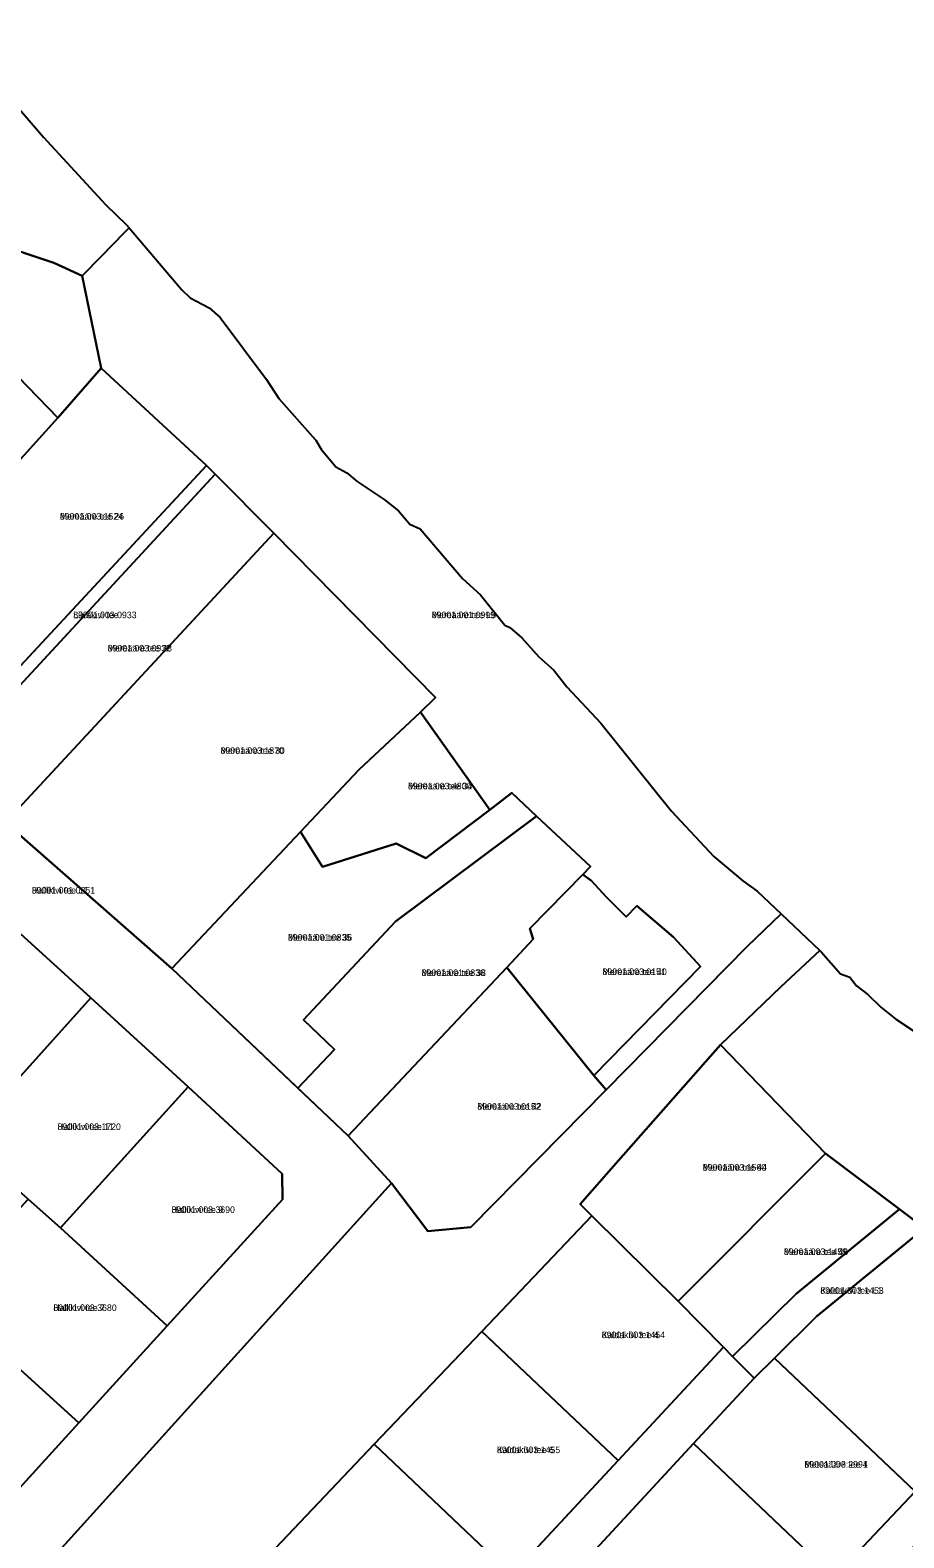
# Model space of a CAD drawing. Extents: x 526849 to 562296, y 6591741 to 6618546.
# Drawn here: x 550573.7 to 550773.8, y 6599050.2 to 6599395.6 of the extents above; entities that cross this region are included whole.
import ezdxf

# ---------------------------------------------------------------- set-up
doc = ezdxf.new("R2010")
doc.units = 0
for name, color, linetype in [('L_AADRESS', 7, 'Continuous'), ('PIIR', 7, 'Continuous'), ('TUNNUS', 7, 'Continuous')]:
    doc.layers.add(name, color=color, linetype=linetype)

msp = doc.modelspace()

# ---------------------------------------------------------------- linework, layer by layer
at = {"layer": 'PIIR'}
for points in [[(550549.04, 6599351.83), (550528.35, 6599369.9), (550549.32, 6599389.11), (550555.84, 6599395.08), (550556.4, 6599395.59), (550567.95, 6599381.35), (550576.84, 6599371.11), (550590.97, 6599355.63), (550595.81, 6599351.02), (550596.43, 6599350.3), (550595.36, 6599349.21), (550590.01, 6599343.77), (550585.65, 6599339.33), (550579.2, 6599342.29), (550572.05, 6599344.67), (550552.5, 6599350.29)], [(550702.85, 6599156.09), (550727.28, 6599181.05), (550721.06, 6599187.81), (550712.73, 6599194.98), (550710.23, 6599192.48), (550705.64, 6599197.07), (550702.3, 6599200.67), (550700.35, 6599202.18), (550702.06, 6599203.99), (550689.74, 6599215.54), (550684.09, 6599220.83), (550679.06, 6599217), (550663.17, 6599239.38), (550666.56, 6599242.67), (550629.58, 6599280.38), (550616.14, 6599293.84), (550614.16, 6599295.87), (550590.03, 6599318.17), (550585.65, 6599339.33), (550590.01, 6599343.77), (550595.36, 6599349.21), (550596.43, 6599350.3), (550608.51, 6599336.1), (550610.42, 6599334.28), (550614.71, 6599331.97), (550617.25, 6599329.75), (550627.88, 6599315.54), (550630.74, 6599311.18), (550638.44, 6599302.46), (550639.15, 6599301.65), (550640.42, 6599299.59), (550643.72, 6599295.57), (550646.26, 6599294.19), (550648.64, 6599292.18), (550654.83, 6599288.05), (550658.11, 6599285.46), (550660.7, 6599282.44), (550663.08, 6599281.33), (550672.77, 6599269.96), (550676.9, 6599266.2), (550682.5, 6599259.27), (550683.62, 6599258.74), (550686.37, 6599256.36), (550690.23, 6599252.02), (550693.67, 6599249), (550696.69, 6599245.14), (550704.47, 6599236.83), (550720.66, 6599216.67), (550730.34, 6599206.3), (550736.96, 6599200.74), (550740.29, 6599198.36), (550745.79, 6599193.13), (550737.98, 6599185.65), (550705.7, 6599152.83)], [(550510.77, 6599309.88), (550541.54, 6599342.64), (550559.43, 6599328.07), (550580.1, 6599306.74), (550556.65, 6599280.86), (550550.6, 6599274.25)], [(550580.1, 6599306.74), (550590.03, 6599318.17), (550614.16, 6599295.87), (550565.51, 6599243.53), (550546.92, 6599260.6), (550561.44, 6599276.48), (550556.65, 6599280.87)], [(550614.16, 6599295.87), (550616.14, 6599293.84), (550553.42, 6599226.1), (550551.1, 6599228), (550565.51, 6599243.53)], [(550616.14, 6599293.84), (550629.58, 6599280.38), (550568.13, 6599214.03), (550553.42, 6599226.1)], [(550666.56, 6599242.67), (550663.17, 6599239.38), (550649.05, 6599226.15), (550606.23, 6599180.62), (550568.13, 6599214.03), (550629.58, 6599280.38)], [(550649.05, 6599226.15), (550663.17, 6599239.38), (550679.06, 6599217), (550664.35, 6599205.91), (550657.54, 6599209.25), (550640.71, 6599203.94), (550635.68, 6599211.93)], [(550635.09, 6599153.18), (550606.23, 6599180.62), (550635.68, 6599211.93), (550640.71, 6599203.94), (550657.54, 6599209.25), (550664.35, 6599205.91), (550679.06, 6599217), (550684.09, 6599220.83), (550689.74, 6599215.54), (550657.46, 6599191.39), (550636.32, 6599168.88), (550643.49, 6599162.06)], [(550657.46, 6599191.39), (550689.74, 6599215.54), (550702.06, 6599203.99), (550700.35, 6599202.18), (550688.21, 6599189.79), (550688.99, 6599187.33), (550682.89, 6599180.84), (550646.61, 6599142.26), (550635.09, 6599153.18), (550643.49, 6599162.06), (550636.32, 6599168.88)], [(550682.89, 6599180.84), (550688.99, 6599187.33), (550688.21, 6599189.79), (550700.35, 6599202.18), (550702.3, 6599200.67), (550705.64, 6599197.07), (550710.23, 6599192.48), (550712.73, 6599194.98), (550721.06, 6599187.81), (550727.28, 6599181.05), (550702.85, 6599156.09)], [(550587.67, 6599173.92), (550558.23, 6599141.18), (550550.11, 6599132.57), (550556.45, 6599126.81), (550543.75, 6599112.69), (550515.18, 6599138.68), (550528.42, 6599153.26), (550536.04, 6599161.3), (550540.8, 6599166.48), (550548.07, 6599175.04), (550565.46, 6599194.05)], [(550702.85, 6599156.09), (550705.7, 6599152.83), (550674.7, 6599121.39), (550664.84, 6599120.43), (550656.49, 6599131.43), (550646.61, 6599142.26), (550682.89, 6599180.84)], [(550573.29, 6599127.75), (550564.86, 6599135.15), (550556.45, 6599126.81), (550550.11, 6599132.57), (550558.23, 6599141.18), (550587.67, 6599173.92), (550609.92, 6599153.53), (550580.7, 6599121.23)], [(550755.88, 6599138.22), (550722.16, 6599104.4), (550702.4, 6599123.99), (550699.72, 6599126.6), (550708.47, 6599136.67), (550731.84, 6599163.13)], [(550631.49, 6599133.6), (550631.57, 6599127.67), (550605.11, 6599098.78), (550580.7, 6599121.23), (550609.92, 6599153.53)], [(550755.88, 6599138.22), (550772.85, 6599125.45), (550749.19, 6599106.08), (550734.64, 6599091.74), (550732.57, 6599093.84), (550722.16, 6599104.4)], [(550580.7, 6599121.23), (550605.11, 6599098.78), (550584.88, 6599076.56), (550553, 6599105.5), (550573.29, 6599127.75)], [(550734.64, 6599091.74), (550749.19, 6599106.08), (550772.85, 6599125.45), (550778.61, 6599121.12), (550753.87, 6599100.87), (550744.26, 6599091.38), (550739.56, 6599086.74)], [(550677.17, 6599097.47), (550702.4, 6599123.99), (550722.16, 6599104.4), (550732.57, 6599093.84), (550708.39, 6599067.87)], [(550753.87, 6599100.87), (550778.61, 6599121.12), (550810.71, 6599097.21), (550776.42, 6599060.82), (550744.26, 6599091.38)], [(550647.29, 6598924.33), (550671.83, 6598950.06), (550691, 6598970.16), (550695.83, 6598975.29), (550726.95, 6599008.32), (550757.9, 6599041.17), (550776.42, 6599060.82), (550810.71, 6599097.21), (550835.74, 6599107.84), (550817.42, 6599092.12), (550794.95, 6599068.26), (550730.49, 6598999.81), (550671.85, 6598937.55), (550653.47, 6598918.39)], [(550553, 6599105.5), (550584.88, 6599076.56), (550566.59, 6599056.47), (550562.29, 6599056.43), (550532.65, 6599083.45)], [(550652.57, 6599071.62), (550677.17, 6599097.47), (550708.39, 6599067.87), (550684.05, 6599041.72)], [(550732.57, 6599093.84), (550734.64, 6599091.74), (550739.56, 6599086.74), (550725.7, 6599071.77), (550694.92, 6599038.5), (550663.72, 6599004.78), (550663.17, 6599004.19), (550640.31, 6598980.12), (550611.24, 6598949.51), (550609.79, 6598950.89), (550633.53, 6598975.89), (550626.28, 6598982.77), (550636.59, 6598993.67), (550638.04, 6598992.29), (550656.06, 6599011.65), (550684.05, 6599041.72), (550708.39, 6599067.87)], [(550757.9, 6599041.17), (550725.7, 6599071.77), (550739.56, 6599086.74), (550744.26, 6599091.38), (550776.42, 6599060.82)], [(550624.26, 6599041.87), (550652.57, 6599071.62), (550684.05, 6599041.72), (550656.06, 6599011.65)], [(550694.92, 6599038.5), (550725.7, 6599071.77), (550757.9, 6599041.17), (550726.95, 6599008.32)]]:
    msp.add_lwpolyline(points, close=True, dxfattribs=at)
for points in [[(550572.05, 6599344.67), (550579.2, 6599342.29), (550585.65, 6599339.33), (550590.03, 6599318.17), (550580.1, 6599306.74), (550559.43, 6599328.07)], [(550568.13, 6599214.03), (550606.23, 6599180.65), (550646.61, 6599142.26), (550656.49, 6599131.43), (550566.61, 6599032.03)], [(550566.59, 6599056.47), (550584.88, 6599076.56), (550605.11, 6599098.78), (550631.57, 6599127.67), (550631.49, 6599133.6), (550609.92, 6599153.53), (550587.67, 6599173.92), (550565.46, 6599194.05)], [(550566.61, 6599032.03), (550656.49, 6599131.43), (550664.84, 6599120.43), (550674.7, 6599121.39), (550705.7, 6599152.83), (550737.98, 6599185.65), (550745.79, 6599193.13), (550754.59, 6599184.78), (550745.65, 6599176.4), (550731.84, 6599163.13), (550708.47, 6599136.67), (550699.72, 6599126.6), (550702.4, 6599123.99), (550677.17, 6599097.47), (550652.57, 6599071.62), (550624.26, 6599041.87)], [(550778.61, 6599121.12), (550772.85, 6599125.45), (550755.88, 6599138.22), (550731.84, 6599163.13), (550745.65, 6599176.4), (550754.59, 6599184.78), (550754.95, 6599184.44), (550759.37, 6599179.41), (550761.46, 6599178.67), (550762.99, 6599176.66), (550765.58, 6599174.65), (550768.55, 6599171.75), (550772.04, 6599169), (550778.34, 6599164.82)]]:
    msp.add_lwpolyline(points, dxfattribs=at)

# ---------------------------------------------------------------- texts
at = {"layer": 'L_AADRESS'}
for s, p in [('Mereääre tee 26', (550580.54, 6599283.47)), ('Liivakivi tee', (550583.62, 6599260.87)), ('Mereääre tee L5', (550665.72, 6599260.88)), ('Mereääre tee 28', (550591.5, 6599253.25)), ('Mereääre tee 30', (550617.35, 6599229.8)), ('Mereääre tee 34', (550660.29, 6599221.66)), ('Hallikivi tee L1', (550574.12, 6599197.79)), ('Mereääre tee 36', (550632.79, 6599187)), ('Mereääre tee 38', (550663.4, 6599178.9)), ('Mereääre tee 40', (550704.84, 6599179.13)), ('Mereääre tee 42', (550676.16, 6599148.27)), ('Hallikivi tee 11', (550580.02, 6599143.62)), ('Mereääre tee 44', (550727.8, 6599134.31)), ('Hallikivi tee 9', (550606.14, 6599124.62)), ('Mereääre tee 46', (550746.38, 6599114.98)), ('Kaldakivi tee L1', (550754.73, 6599106.09)), ('Hallikivi tee 7', (550579.06, 6599102.15)), ('Kaldakivi tee 4', (550704.65, 6599095.93)), ('Kaldakivi tee 6', (550680.64, 6599069.59)), ('Metsaääre tee 4', (550751.08, 6599066.28))]:
    msp.add_text(s, height=1.5, dxfattribs=at).set_placement(p)
at = {"layer": 'TUNNUS'}
for s, p in [('89001:003:1524', (550580.54, 6599283.47)), ('89001:003:0933', (550583.62, 6599260.87)), ('89001:001:0999', (550665.72, 6599260.88)), ('89001:003:0932', (550591.5, 6599253.25)), ('89001:003:1870', (550617.35, 6599229.8)), ('89001:003:4800', (550660.29, 6599221.66)), ('89001:001:0851', (550574.12, 6599197.79)), ('89001:001:0835', (550632.79, 6599187)), ('89001:001:0836', (550663.4, 6599178.9)), ('89001:003:0151', (550704.84, 6599179.13)), ('89001:003:0152', (550676.16, 6599148.27)), ('89001:003:1720', (550580.02, 6599143.62)), ('89001:003:1560', (550727.8, 6599134.31)), ('89001:003:3690', (550606.14, 6599124.62)), ('89001:003:1459', (550746.38, 6599114.98)), ('89001:003:1453', (550754.73, 6599106.09)), ('89001:003:3680', (550579.06, 6599102.15)), ('89001:003:1454', (550704.65, 6599095.93)), ('89001:003:1455', (550680.64, 6599069.59)), ('89001:003:2991', (550751.08, 6599066.28))]:
    msp.add_text(s, height=1.5, dxfattribs=at).set_placement(p)

doc.saveas('drawing.dxf')
